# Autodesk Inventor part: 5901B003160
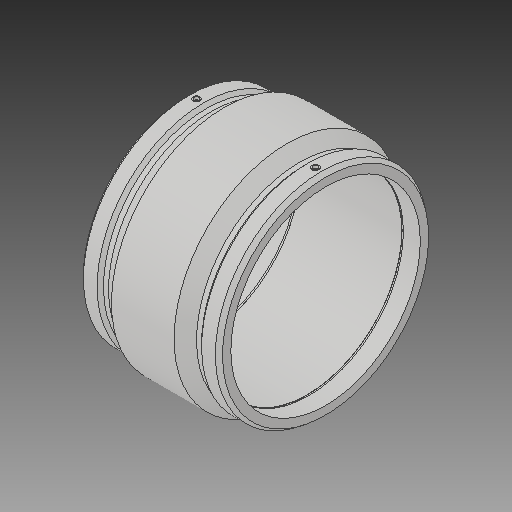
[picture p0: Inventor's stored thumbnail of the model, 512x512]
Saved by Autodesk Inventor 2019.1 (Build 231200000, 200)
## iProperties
Created: 2017-06
Part Number: 5901B003160
Material: Generic
Description: PLASSON IPS COUPLER 16''
Document SubType Name: Modeling
Designer: KIM
Mass: 8622.19 g
Surface Area: 6772.47 cm^2
Volume: 8622.19 cm^3
Density: 1 g/cm^3
Appearance: Default
Author: KIM
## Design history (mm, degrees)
derived "5901B.ipt"
feature "Solid1::5901B.ipt"
tag "TaggingFeature1"
body "Solid1"
other parameters: "d0" = 297.18, "d1" = 404.6, "d2" = 482.6, "d3" = 148.082, "d4" = 74.295, "d5" = 434.34, "d6" = 323.68, "d7" = 404.6, "d8" = 168 deg, "d10" = 59.2328, "d11" = 19.74427, "d13" = 297.18, "d14" = 17.6296, "d18" = 404.6, "d19" = 3.52592, "d20" = 168 deg, "d22" = 453.644, "d23" = 482.6, "d24" = 440.03468, "d25" = 135 deg, "d26" = 133.731, "d27" = 135 deg, "d29" = 227.584, "d30" = 15, "d31" = 104.013, "d34" = 5 deg, "d35" = 15, "d39" = 5 deg, "d41" = 4, "d42" = 14, "d43" = 0, "d45" = 4, "d46" = 14, "d47" = 0, "d48" = 3, "d49" = 0, "d50" = 3, "d51" = 0, "d52" = 42.94378, "d53" = 10.73595, "d55" = 148.082, "d_" = 404.6, "L_" = 297.18, "L_1" = 148.082, "D_" = 482.6, "A_" = 227.584, "d_2" = 12, "B_" = 227.584
